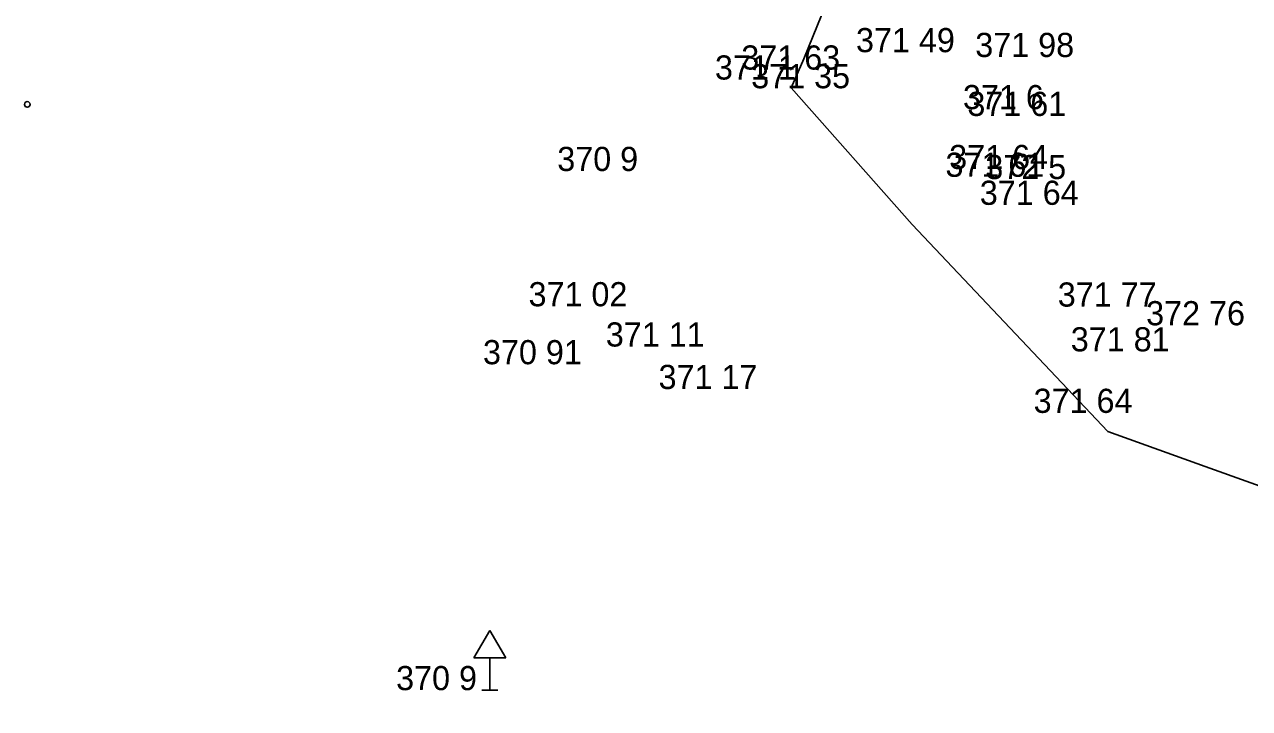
# Model space of a CAD drawing. Extents: x -688316 to -688024, y -973785 to -973591.
# Drawn here: x -688090.26 to -688052.25, y -973762.27 to -973741.03 of the extents above; entities that cross this region are included whole.
import ezdxf

# ---------------------------------------------------------------- set-up
doc = ezdxf.new("R2010")
doc.units = 0
for name, color, linetype in [('Vrstva 3', 7, 'Continuous'), ('Vrstva 34', 7, 'Continuous'), ('Vrstva 58', 7, 'Continuous')]:
    doc.layers.add(name, color=color, linetype=linetype)

# ---------------------------------------------------------------- blocks, each defined once
blk = doc.blocks.new('DZ')
at = {"layer": 'Vrstva 34'}
for p, q in [((-5, 10), (0, 18.5)), ((0, 18.5), (5, 10)), ((-5, 10), (5, 10)), ((0, 0), (0, 10)), ((-2.49, 0), (2.49, 0))]:
    blk.add_line(p, q, dxfattribs=at)
blk = doc.blocks.new('B_NESP')
at = {"layer": 'Vrstva 58'}
blk.add_circle((0, 0), 0.875, dxfattribs=at)

msp = doc.modelspace()

# ---------------------------------------------------------------- linework, layer by layer
at = {"layer": 'Vrstva 3'}
for points in [[(-688066.073, -973742.092), (-688062.05, -973732.17), (-688060.52, -973728.33), (-688065.89, -973725.27), (-688070.75, -973722.38), (-688071.97, -973725.53)], [(-688066.073, -973742.092), (-688062.05, -973732.17), (-688060.52, -973728.33), (-688065.89, -973725.27), (-688070.75, -973722.38), (-688071.97, -973725.53)], [(-688066.073, -973742.092), (-688062.05, -973732.17), (-688060.52, -973728.33), (-688065.89, -973725.27), (-688070.75, -973722.38), (-688071.97, -973725.53)], [(-688066.073, -973742.092), (-688062.05, -973732.17), (-688060.52, -973728.33), (-688065.89, -973725.27), (-688070.75, -973722.38), (-688071.97, -973725.53)], [(-688032.63, -973762.27), (-688053.63, -973754.76), (-688056.65, -973753.67), (-688062.72, -973747.24), (-688066.47, -973743), (-688066.073, -973742.092)], [(-688032.63, -973762.27), (-688053.63, -973754.76), (-688056.65, -973753.67), (-688062.72, -973747.24), (-688066.47, -973743), (-688066.073, -973742.092)], [(-688032.63, -973762.27), (-688053.63, -973754.76), (-688056.65, -973753.67), (-688062.72, -973747.24), (-688066.47, -973743), (-688066.073, -973742.092)], [(-688032.63, -973762.27), (-688053.63, -973754.76), (-688056.65, -973753.67), (-688062.72, -973747.24), (-688066.47, -973743), (-688066.073, -973742.092)]]:
    msp.add_lwpolyline(points, dxfattribs=at)

# ---------------------------------------------------------------- block references
at = {"layer": 'Vrstva 34', "xscale": 0.1, "yscale": 0.10000000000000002}
msp.add_blockref('DZ', (-688075.82, -973761.7), dxfattribs=at)
msp.add_blockref('DZ', (-688075.82, -973761.7), dxfattribs=at)
at = {"layer": 'Vrstva 58', "xscale": 0.1, "yscale": 0.10000000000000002}
msp.add_blockref('B_NESP', (-688090.17, -973743.51), dxfattribs=at)
msp.add_blockref('B_NESP', (-688090.17, -973743.51), dxfattribs=at)

# ---------------------------------------------------------------- texts
at = {"layer": 'Vrstva 3'}
for s, p in [('371 49 ', (-688064.459, -973741.89)), ('371 49 ', (-688064.459, -973741.89)), ('371 49 ', (-688064.459, -973741.89)), ('371 49 ', (-688064.459, -973741.89)), ('371 49 ', (-688064.459, -973741.89)), ('371 49 ', (-688064.459, -973741.89)), ('371 49 ', (-688064.459, -973741.89)), ('371 98 ', (-688060.759, -973742.04)), ('371 98 ', (-688060.759, -973742.04)), ('371 98 ', (-688060.759, -973742.04)), ('371 98 ', (-688060.759, -973742.04)), ('371 98 ', (-688060.759, -973742.04)), ('371 98 ', (-688060.759, -973742.04)), ('371 98 ', (-688060.759, -973742.04)), ('371 63 ', (-688068.018, -973742.43)), ('371 63 ', (-688068.018, -973742.43)), ('371 63 ', (-688068.018, -973742.43)), ('371 63 ', (-688068.018, -973742.43)), ('371 63 ', (-688068.018, -973742.43)), ('371 63 ', (-688068.018, -973742.43)), ('371 63 ', (-688068.018, -973742.43)), ('371 1  ', (-688068.836, -973742.74)), ('371 1  ', (-688068.836, -973742.74)), ('371 1  ', (-688068.836, -973742.74)), ('371 1  ', (-688068.836, -973742.74)), ('371 1  ', (-688068.836, -973742.74)), ('371 1  ', (-688068.836, -973742.74)), ('371 1  ', (-688068.836, -973742.74)), ('371 35 ', (-688067.711, -973743.01)), ('371 35 ', (-688067.711, -973743.01)), ('371 35 ', (-688067.711, -973743.01)), ('371 35 ', (-688067.711, -973743.01)), ('371 35 ', (-688067.711, -973743.01)), ('371 35 ', (-688067.711, -973743.01)), ('371 35 ', (-688067.711, -973743.01)), ('371 6  ', (-688061.141, -973743.66)), ('371 6  ', (-688061.141, -973743.66)), ('371 6  ', (-688061.141, -973743.66)), ('371 6  ', (-688061.141, -973743.66)), ('371 6  ', (-688061.141, -973743.66)), ('371 6  ', (-688061.141, -973743.66)), ('371 6  ', (-688061.141, -973743.66)), ('371 61 ', (-688061.004, -973743.87)), ('371 61 ', (-688061.004, -973743.87)), ('371 61 ', (-688061.004, -973743.87)), ('371 61 ', (-688061.004, -973743.87)), ('371 61 ', (-688061.004, -973743.87)), ('371 61 ', (-688061.004, -973743.87)), ('371 61 ', (-688061.004, -973743.87)), ('370 9  ', (-688073.728, -973745.58)), ('370 9  ', (-688073.728, -973745.58)), ('370 9  ', (-688073.728, -973745.58)), ('370 9  ', (-688073.728, -973745.58)), ('370 9  ', (-688073.728, -973745.58)), ('370 9  ', (-688073.728, -973745.58)), ('370 9  ', (-688073.728, -973745.58)), ('371 64 ', (-688061.568, -973745.52)), ('371 64 ', (-688061.568, -973745.52)), ('371 64 ', (-688061.568, -973745.52)), ('371 64 ', (-688061.568, -973745.52)), ('371 64 ', (-688061.568, -973745.52)), ('371 64 ', (-688061.568, -973745.52)), ('371 64 ', (-688061.568, -973745.52)), ('371 61 ', (-688061.684, -973745.76)), ('371 61 ', (-688061.684, -973745.76)), ('371 61 ', (-688061.684, -973745.76)), ('371 61 ', (-688061.684, -973745.76)), ('371 61 ', (-688061.684, -973745.76)), ('371 61 ', (-688061.684, -973745.76)), ('371 61 ', (-688061.684, -973745.76)), ('372 5  ', (-688060.448, -973745.83)), ('372 5  ', (-688060.448, -973745.83)), ('372 5  ', (-688060.448, -973745.83)), ('372 5  ', (-688060.448, -973745.83)), ('372 5  ', (-688060.448, -973745.83)), ('372 5  ', (-688060.448, -973745.83)), ('372 5  ', (-688060.448, -973745.83)), ('371 64 ', (-688060.618, -973746.63)), ('371 64 ', (-688060.618, -973746.63)), ('371 64 ', (-688060.618, -973746.63)), ('371 64 ', (-688060.618, -973746.63)), ('371 64 ', (-688060.618, -973746.63)), ('371 64 ', (-688060.618, -973746.63)), ('371 64 ', (-688060.618, -973746.63)), ('371 02 ', (-688074.619, -973749.78)), ('371 02 ', (-688074.619, -973749.78)), ('371 02 ', (-688074.619, -973749.78)), ('371 02 ', (-688074.619, -973749.78)), ('371 02 ', (-688074.619, -973749.78)), ('371 02 ', (-688074.619, -973749.78)), ('371 02 ', (-688074.619, -973749.78)), ('371 77 ', (-688058.199, -973749.79)), ('371 77 ', (-688058.199, -973749.79)), ('371 77 ', (-688058.199, -973749.79)), ('371 77 ', (-688058.199, -973749.79)), ('371 77 ', (-688058.199, -973749.79)), ('371 77 ', (-688058.199, -973749.79)), ('371 77 ', (-688058.199, -973749.79)), ('372 76 ', (-688055.457, -973750.37)), ('372 76 ', (-688055.457, -973750.37)), ('372 76 ', (-688055.457, -973750.37)), ('372 76 ', (-688055.457, -973750.37)), ('372 76 ', (-688055.457, -973750.37)), ('372 76 ', (-688055.457, -973750.37)), ('372 76 ', (-688055.457, -973750.37)), ('371 11 ', (-688072.221, -973751.03)), ('371 11 ', (-688072.221, -973751.03)), ('371 11 ', (-688072.221, -973751.03)), ('371 11 ', (-688072.221, -973751.03)), ('371 11 ', (-688072.221, -973751.03)), ('371 11 ', (-688072.221, -973751.03)), ('371 11 ', (-688072.221, -973751.03)), ('371 81 ', (-688057.795, -973751.18)), ('371 81 ', (-688057.795, -973751.18)), ('371 81 ', (-688057.795, -973751.18)), ('371 81 ', (-688057.795, -973751.18)), ('371 81 ', (-688057.795, -973751.18)), ('371 81 ', (-688057.795, -973751.18)), ('371 81 ', (-688057.795, -973751.18)), ('370 91 ', (-688076.033, -973751.58)), ('370 91 ', (-688076.033, -973751.58)), ('370 91 ', (-688076.033, -973751.58)), ('370 91 ', (-688076.033, -973751.58)), ('370 91 ', (-688076.033, -973751.58)), ('370 91 ', (-688076.033, -973751.58)), ('370 91 ', (-688076.033, -973751.58)), ('371 17 ', (-688070.585, -973752.35)), ('371 17 ', (-688070.585, -973752.35)), ('371 17 ', (-688070.585, -973752.35)), ('371 17 ', (-688070.585, -973752.35)), ('371 17 ', (-688070.585, -973752.35)), ('371 17 ', (-688070.585, -973752.35)), ('371 17 ', (-688070.585, -973752.35)), ('371 64 ', (-688058.948, -973753.09)), ('371 64 ', (-688058.948, -973753.09)), ('371 64 ', (-688058.948, -973753.09)), ('371 64 ', (-688058.948, -973753.09)), ('371 64 ', (-688058.948, -973753.09)), ('371 64 ', (-688058.948, -973753.09)), ('371 64 ', (-688058.948, -973753.09)), ('370 9  ', (-688078.728, -973761.7)), ('370 9  ', (-688078.728, -973761.7)), ('370 9  ', (-688078.728, -973761.7)), ('370 9  ', (-688078.728, -973761.7)), ('370 9  ', (-688078.728, -973761.7)), ('370 9  ', (-688078.728, -973761.7)), ('370 9  ', (-688078.728, -973761.7))]:
    msp.add_text(s, height=0.75, dxfattribs=at).set_placement(p)

doc.saveas('drawing.dxf')
